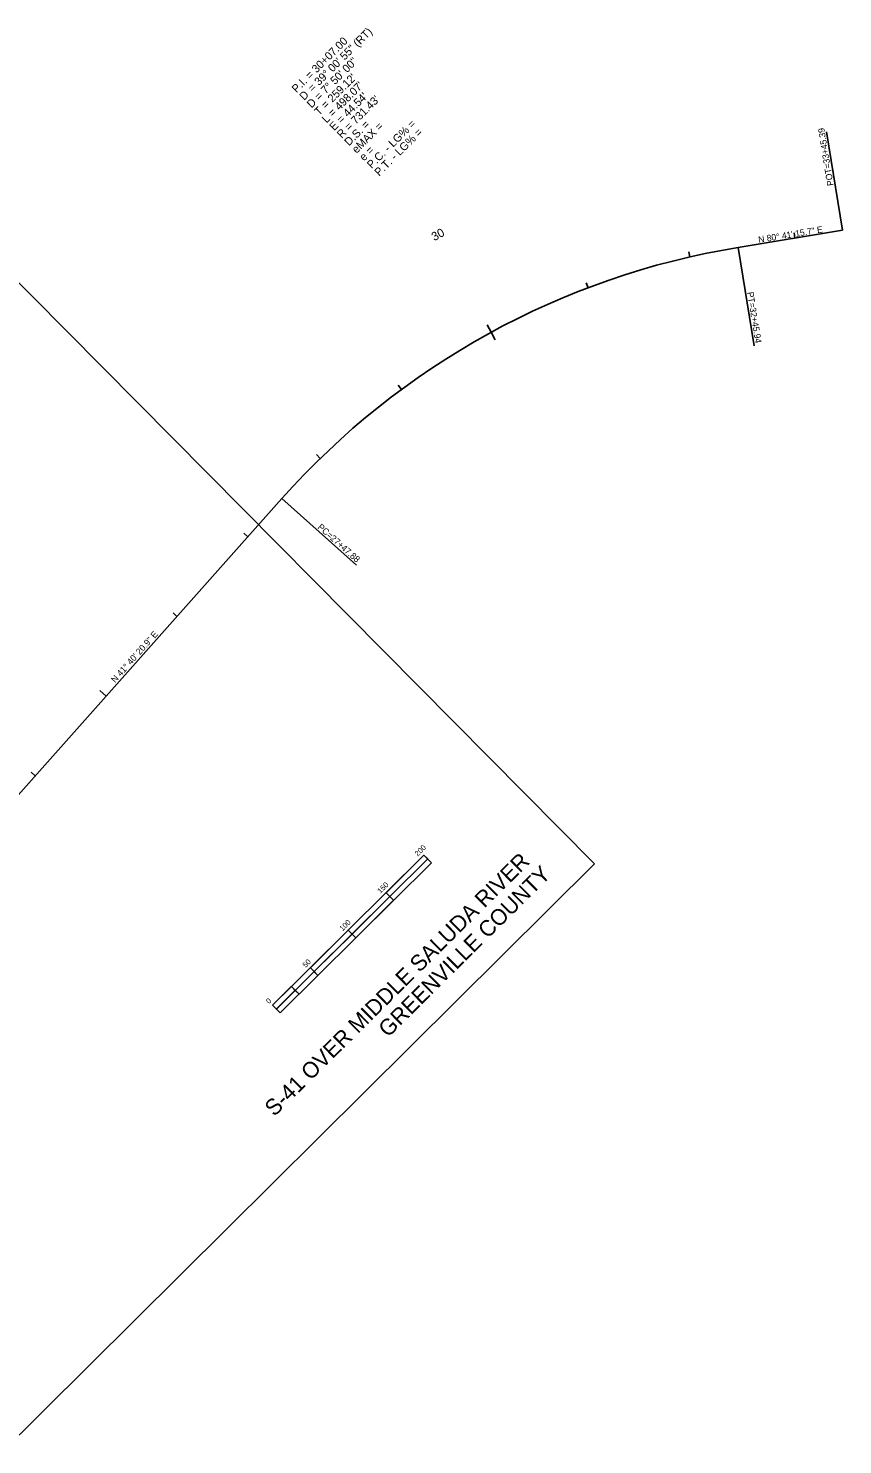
# Model space of a CAD drawing. Extents: x 1539042 to 1541327, y 1198578 to 1200629.
# Drawn here: x 1540563 to 1541327, y 1199301 to 1200629 of the extents above; entities that cross this region are included whole.
import ezdxf

# ---------------------------------------------------------------- set-up
doc = ezdxf.new("R2010")
doc.units = 0
for name, color, linetype in [('RD_HC_Cl', 7, 'Continuous'), ('RD_HC_Data', 7, 'Continuous'), ('RD_HC_Data_Tic', 7, 'Continuous'), ('RD_HC_TX_Sta50', 7, 'Continuous'), ('RD_SHT_ShtClip', 7, 'Continuous'), ('RD_SHT_TX', 7, 'Continuous')]:
    doc.layers.add(name, color=color, linetype=linetype)

msp = doc.modelspace()

# ---------------------------------------------------------------- linework, layer by layer
at = {"layer": 'RD_HC_Cl'}
for p, q in [((1541228.9, 1200423.5), (1541327, 1200439.6)), ((1540452.6, 1199796.6), (1540800.9, 1200188))]:
    msp.add_line(p, q, dxfattribs=at)
msp.add_arc((1541347.3, 1199701.7), 731.4, 99.3123, 138.3275, dxfattribs=at)
at = {"layer": 'RD_HC_Data'}
for p, q in [((1541327, 1200439.6), (1541311.9, 1200532)), ((1541228.9, 1200423.5), (1541244.1, 1200331.1)), ((1540800.9, 1200188), (1540870.9, 1200125.7))]:
    msp.add_line(p, q, dxfattribs=at)
at = {"layer": 'RD_HC_Data_Tic'}
for p, q in [((1541282.3, 1200432.2), (1541281.4, 1200437.2)), ((1541183.8, 1200414.6), (1541182.7, 1200419.5)), ((1541088.2, 1200385.7), (1541086.4, 1200390.4)), ((1540997.4, 1200344), (1540993.6, 1200351)), ((1541001.2, 1200337), (1540997.4, 1200344)), ((1540913.1, 1200290.3), (1540910.1, 1200294.4)), ((1540836.9, 1200225.7), (1540833.4, 1200229.2)), ((1540769.1, 1200152.2), (1540765.4, 1200155.6)), ((1540702.6, 1200077.5), (1540698.9, 1200080.9)), ((1540636.1, 1200002.8), (1540630.1, 1200008.2)), ((1540569.6, 1199928.1), (1540565.9, 1199931.5))]:
    msp.add_line(p, q, dxfattribs=at)
at = {"layer": 'RD_SHT_ShtClip'}
for p, q in [((1540319.7, 1200626.7), (1541094.3, 1199845.6)), ((1541094.3, 1199845.6), (1539816.2, 1198578.2))]:
    msp.add_line(p, q, dxfattribs=at)
at = {"layer": 'RD_SHT_TX'}
for p, q in [((1540792.3, 1199713), (1540934.2, 1199853.7)), ((1540799.3, 1199705.9), (1540941.3, 1199846.6)), ((1540831.3, 1199744.6), (1540937.8, 1199850.2)), ((1540934.2, 1199853.7), (1540941.3, 1199846.6)), ((1540938.5, 1199849.5), (1540938.5, 1199849.5)), ((1540939.2, 1199848.8), (1540939.2, 1199848.8)), ((1540939.9, 1199848.1), (1540939.9, 1199848.1)), ((1540940.6, 1199847.4), (1540940.6, 1199847.4)), ((1540898.7, 1199818.5), (1540905.8, 1199811.4)), ((1540905.8, 1199811.4), (1540905.8, 1199811.4)), ((1540863.3, 1199783.3), (1540870.3, 1199776.2)), ((1540795.8, 1199709.4), (1540831.3, 1199744.6)), ((1540827.8, 1199748.1), (1540834.8, 1199741)), ((1540834.8, 1199741), (1540834.8, 1199741)), ((1540810, 1199730.6), (1540817.1, 1199723.5)), ((1540792.3, 1199713), (1540799.3, 1199705.9))]:
    msp.add_line(p, q, dxfattribs=at)
for points in [[(1540898.7, 1199818.5), (1540934.2, 1199853.7), (1540937.8, 1199850.2), (1540902.3, 1199815)], [(1540866.8, 1199779.8), (1540902.3, 1199815), (1540905.8, 1199811.4), (1540870.3, 1199776.2)], [(1540827.8, 1199748.1), (1540863.3, 1199783.4), (1540866.8, 1199779.8), (1540831.3, 1199744.6)], [(1540813.5, 1199727), (1540831.3, 1199744.6), (1540834.8, 1199741), (1540817.1, 1199723.5)], [(1540792.3, 1199713), (1540810, 1199730.6), (1540813.6, 1199726.9), (1540795.9, 1199709.3)]]:
    msp.add_lwpolyline(points, close=True, dxfattribs=at)

# ---------------------------------------------------------------- texts
at = {"layer": 'RD_HC_Data'}
for s, height, rotation, p in [('    = 39%%d 00\' 55" (RT)', 7.5, 44.7604, (1540821.8, 1200560.8)), ('P.I. = 30+07.00', 7.5, 44.7604, (1540814.7, 1200567.9)), ('D = 7%%d 50\' 00"', 7.5, 44.7604, (1540828.8, 1200553.7)), ("T = 259.12'", 7.5, 44.7604, (1540835.9, 1200546.6)), ("L = 498.07'", 7.5, 44.7604, (1540842.9, 1200539.5)), ('D', 7.5, 44.7604, (1540821.8, 1200560.8)), ("E = 44.54'", 7.5, 44.7604, (1540850, 1200532.4)), ("R = 731.43'", 7.5, 44.7604, (1540857, 1200525.3)), ('D.S. = ', 7.5, 44.7604, (1540864, 1200518.2)), ('eMAX = ', 7.5, 44.7604, (1540871.1, 1200511.1)), ('P.C. - LG% = ', 7.5, 44.7604, (1540885.2, 1200496.9)), ('P.T. - LG% = ', 7.5, 44.7604, (1540892.2, 1200489.8)), ('POT=33+45.39', 6, 99.3123, (1541318.6, 1200481.7)), ('e = ', 7.5, 44.7604, (1540878.1, 1200504)), ('N 80%%d 41\' 15.7" E', 6, 9.3123, (1541248.4, 1200427.7)), ('PT=32+45.94', 6, 279.3123, (1541237.3, 1200381.3)), ('PC=27+47.88', 6, 318.3275, (1540834, 1200160.5)), ('N 41%%d 40\' 20.9" E', 6, 48.3275, (1540644.6, 1200014.9))]:
    msp.add_text(s, height=height, rotation=rotation, dxfattribs=at).set_placement(p)
at = {"layer": 'RD_HC_TX_Sta50'}
msp.add_text('30', height=8, rotation=28.5779, dxfattribs=at).set_placement((1540944, 1200429.3))
at = {"layer": 'RD_SHT_TX'}
for s, height, rotation, p in [('200', 5, 44.7596, (1540928.5, 1199852.3)), ('S-41 OVER MIDDLE SALUDA RIVER', 15, 44.7604, (1540793.9, 1199608.1)), ('GREENVILLE COUNTY', 15, 44.7604, (1540900.6, 1199682.2)), ('150', 5, 44.7564, (1540893.4, 1199817.4)), ('100', 5, 44.7578, (1540857.9, 1199782.2)), ('50', 5, 44.7604, (1540823.3, 1199747.9)), ('0', 5, 44.757, (1540789, 1199714))]:
    msp.add_text(s, height=height, rotation=rotation, dxfattribs=at).set_placement(p)

doc.saveas('drawing.dxf')
